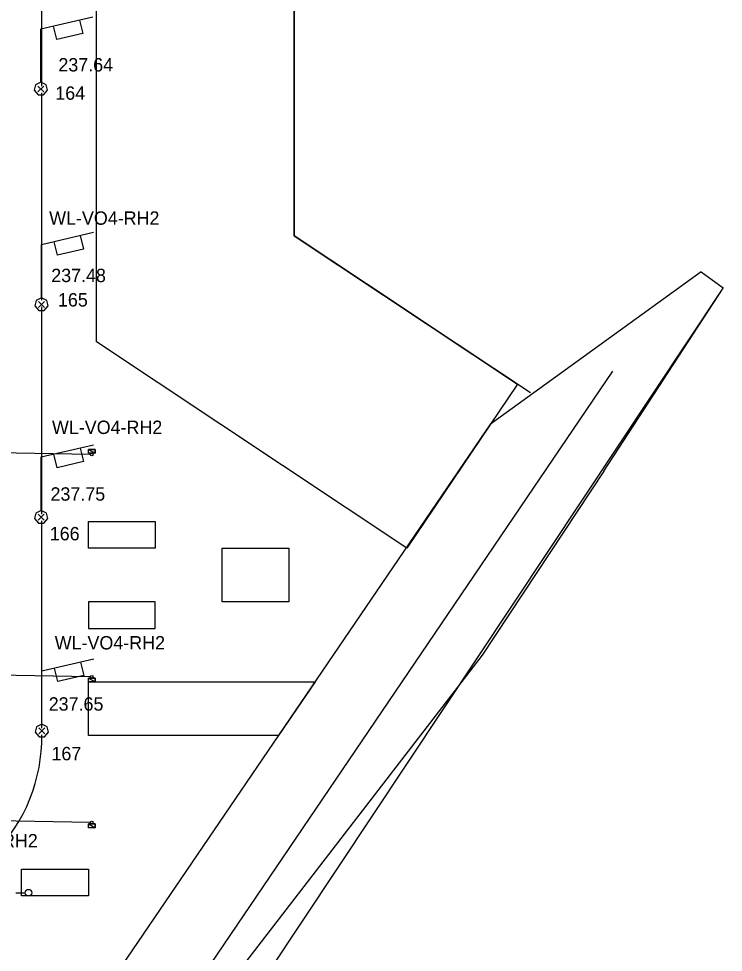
# Model space of a CAD drawing. Extents: x -264222 to -263592, y -1242345 to -1242048.
# Drawn here: x -263787.2 to -263734.5, y -1242254.6 to -1242184.8 of the extents above; entities that cross this region are included whole.
import ezdxf

# ---------------------------------------------------------------- set-up
doc = ezdxf.new("R2010")
doc.units = 0
for name, color, linetype in [('BOD_CISLO', 7, 'Continuous'), ('BOD_SYMBOL', 7, 'Continuous'), ('BOD_VYSKA', 7, 'Continuous'), ('KFA_2D_SITUACIA_DSP', 7, 'Continuous'), ('KFA_SO_62-1_VO_LAMPY_MERANE', 7, 'Continuous'), ('KFA_SO_62-1_VO_POPIS_LAMP_PROJEKT', 7, 'Continuous'), ('KFA_SO_62-1_VO_TRASA_KABLOV_PROJEKT', 7, 'Continuous')]:
    doc.layers.add(name, color=color, linetype=linetype)

msp = doc.modelspace()

# ---------------------------------------------------------------- linework, layer by layer
at = {"layer": 'BOD_SYMBOL'}
for p, q in [((-263785.745, -1242190.259), (-263785.303, -1242189.817)), ((-263785.303, -1242190.259), (-263785.745, -1242189.817)), ((-263785.697, -1242206.378), (-263785.255, -1242205.936)), ((-263785.255, -1242206.378), (-263785.697, -1242205.936)), ((-263785.713, -1242222.277), (-263785.271, -1242221.835)), ((-263785.271, -1242222.277), (-263785.713, -1242221.835)), ((-263785.668, -1242238.262), (-263785.226, -1242237.82)), ((-263785.226, -1242238.262), (-263785.668, -1242237.82))]:
    msp.add_line(p, q, dxfattribs=at)
at = {"layer": 'KFA_2D_SITUACIA_DSP'}
for p, q in [((-263766.58, -1242201.01), (-263766.58, -1242144.85)), ((-263758.42, -1242206.43), (-263766.58, -1242201.01)), ((-263736.134, -1242203.7), (-263751.891, -1242215.1)), ((-263736.134, -1242203.7), (-263734.475, -1242204.91)), ((-263822.88, -1242337.914), (-263734.49, -1242204.937)), ((-263757.19, -1242207.25), (-263758.42, -1242206.43)), ((-263748.89, -1242212.77), (-263757.19, -1242207.25)), ((-263794.898, -1242288.032), (-263742.736, -1242211.145)), ((-263798.899, -1242284.125), (-263751.864, -1242215.081)), ((-263751.891, -1242215.1), (-263751.891, -1242215.1)), ((-263781.968, -1242216.987), (-263781.468, -1242216.987)), ((-263781.968, -1242217.277), (-263781.968, -1242216.987)), ((-263781.968, -1242216.987), (-263781.468, -1242217.277)), ((-263781.968, -1242216.987), (-263781.468, -1242217.277)), ((-263781.468, -1242216.987), (-263781.968, -1242216.987)), ((-263781.468, -1242216.987), (-263781.468, -1242217.277)), ((-263781.468, -1242217.277), (-263781.468, -1242216.987)), ((-263781.818, -1242217.375), (-263790.409, -1242217.218)), ((-263781.468, -1242217.277), (-263781.968, -1242217.277)), ((-263743.421, -1242218.608), (-263752.521, -1242232.37)), ((-263781.968, -1242228.382), (-263781.968, -1242230.382)), ((-263776.968, -1242228.382), (-263781.968, -1242228.382)), ((-263776.968, -1242230.382), (-263776.968, -1242228.382)), ((-263781.968, -1242230.382), (-263776.968, -1242230.382)), ((-263752.521, -1242232.37), (-263782.166, -1242270.821)), ((-263781.818, -1242233.99), (-263790.714, -1242233.827)), ((-263781.968, -1242234.092), (-263781.468, -1242234.092)), ((-263781.968, -1242234.382), (-263781.968, -1242234.092)), ((-263781.968, -1242234.092), (-263781.468, -1242234.382)), ((-263781.968, -1242234.092), (-263781.468, -1242234.382)), ((-263781.468, -1242234.092), (-263781.968, -1242234.092)), ((-263781.468, -1242234.382), (-263781.968, -1242234.382)), ((-263781.968, -1242234.382), (-263771.968, -1242234.382)), ((-263781.968, -1242238.382), (-263781.968, -1242234.382)), ((-263781.968, -1242234.382), (-263781.968, -1242234.382)), ((-263781.468, -1242234.092), (-263781.468, -1242234.382)), ((-263781.468, -1242234.382), (-263781.468, -1242234.092)), ((-263771.968, -1242234.382), (-263765.013, -1242234.382)), ((-263765.013, -1242234.382), (-263767.738, -1242238.382)), ((-263771.968, -1242238.382), (-263781.968, -1242238.382)), ((-263767.738, -1242238.382), (-263771.968, -1242238.382)), ((-263781.818, -1242244.885), (-263790.914, -1242244.718)), ((-263781.968, -1242244.987), (-263781.468, -1242244.987)), ((-263781.968, -1242245.277), (-263781.968, -1242244.987)), ((-263781.968, -1242244.987), (-263781.468, -1242245.277)), ((-263781.968, -1242244.987), (-263781.468, -1242245.277)), ((-263781.468, -1242244.987), (-263781.968, -1242244.987)), ((-263781.468, -1242244.987), (-263781.468, -1242245.277)), ((-263781.468, -1242245.277), (-263781.468, -1242244.987)), ((-263781.468, -1242245.277), (-263781.968, -1242245.277)), ((-263787.393, -1242250.14), (-263786.693, -1242250.14))]:
    msp.add_line(p, q, dxfattribs=at)
for points in [[(-263766.58, -1242083.485), (-263766.58, -1242201.01), (-263749.879, -1242212.113), (-263758.153, -1242224.365), (-263781.364, -1242208.936), (-263781.371, -1242084.903)], [(-263781.968, -1242222.382), (-263776.968, -1242222.382), (-263776.968, -1242224.382), (-263781.968, -1242224.382)], [(-263771.968, -1242224.382), (-263766.968, -1242224.382), (-263766.968, -1242228.382), (-263771.968, -1242228.382)], [(-263786.968, -1242248.382), (-263781.968, -1242248.382), (-263781.968, -1242250.382), (-263786.968, -1242250.382)]]:
    msp.add_lwpolyline(points, close=True, dxfattribs=at)
msp.add_lwpolyline([(-263743.421, -1242218.608), (-263734.49, -1242204.937), (-263734.475, -1242204.91), (-263734.475, -1242204.91)], dxfattribs=at)
for centre, radius in [((-263781.718, -1242217.377), 0.1), ((-263781.718, -1242233.992), 0.1), ((-263781.718, -1242244.887), 0.1), ((-263786.443, -1242250.14), 0.25)]:
    msp.add_circle(centre, radius, dxfattribs=at)
at = {"layer": 'KFA_SO_62-1_VO_LAMPY_MERANE'}
for p, q in [((-263785.574, -1242190.038), (-263785.474, -1242190.038)), ((-263785.524, -1242190.038), (-263785.524, -1242190.038)), ((-263785.526, -1242206.157), (-263785.426, -1242206.157)), ((-263785.476, -1242206.157), (-263785.476, -1242206.157)), ((-263785.542, -1242222.056), (-263785.442, -1242222.056)), ((-263785.492, -1242222.056), (-263785.492, -1242222.056)), ((-263785.497, -1242238.041), (-263785.397, -1242238.041)), ((-263785.447, -1242238.041), (-263785.447, -1242238.041))]:
    msp.add_line(p, q, dxfattribs=at)
for points in [[(-263785.524, -1242189.538), (-263785.924, -1242189.738), (-263786.024, -1242190.138), (-263785.724, -1242190.488), (-263785.324, -1242190.488), (-263785.024, -1242190.138), (-263785.124, -1242189.738), (-263785.524, -1242189.538), (-263785.524, -1242185.538), (-263781.624, -1242184.638)], [(-263782.624, -1242184.888), (-263782.374, -1242185.888), (-263784.324, -1242186.338), (-263784.574, -1242185.338)], [(-263785.476, -1242205.657), (-263785.876, -1242205.857), (-263785.976, -1242206.257), (-263785.676, -1242206.607), (-263785.276, -1242206.607), (-263784.976, -1242206.257), (-263785.076, -1242205.857), (-263785.476, -1242205.657), (-263785.476, -1242201.657), (-263781.576, -1242200.757)], [(-263782.576, -1242201.007), (-263782.326, -1242202.007), (-263784.276, -1242202.457), (-263784.526, -1242201.457)], [(-263785.492, -1242221.556), (-263785.892, -1242221.756), (-263785.992, -1242222.156), (-263785.692, -1242222.506), (-263785.292, -1242222.506), (-263784.992, -1242222.156), (-263785.092, -1242221.756), (-263785.492, -1242221.556), (-263785.492, -1242217.556), (-263781.592, -1242216.656)], [(-263782.592, -1242216.906), (-263782.342, -1242217.906), (-263784.292, -1242218.356), (-263784.542, -1242217.356)], [(-263785.447, -1242237.541), (-263785.847, -1242237.741), (-263785.947, -1242238.141), (-263785.647, -1242238.491), (-263785.247, -1242238.491), (-263784.947, -1242238.141), (-263785.047, -1242237.741), (-263785.447, -1242237.541), (-263785.447, -1242233.541), (-263781.547, -1242232.641)], [(-263782.547, -1242232.891), (-263782.297, -1242233.891), (-263784.247, -1242234.341), (-263784.497, -1242233.341)]]:
    msp.add_lwpolyline(points, dxfattribs=at)
at = {"layer": 'KFA_SO_62-1_VO_TRASA_KABLOV_PROJEKT'}
for p, q in [((-263785.465, -1242174.333), (-263785.465, -1242189.833)), ((-263785.465, -1242190.333), (-263785.465, -1242205.833)), ((-263785.465, -1242206.333), (-263785.465, -1242221.833)), ((-263785.465, -1242222.333), (-263785.465, -1242237.833))]:
    msp.add_line(p, q, dxfattribs=at)
msp.add_arc((-263797.796, -1242238.53), 12.345, 269.80426, 0.91793, dxfattribs=at)

# ---------------------------------------------------------------- texts
at = {"layer": 'BOD_CISLO'}
for s, p in [('164', (-263784.442, -1242190.846)), ('165', (-263784.243, -1242206.305)), ('166', (-263784.854, -1242223.79)), ('167', (-263784.728, -1242240.237))]:
    msp.add_text(s, height=1, dxfattribs=at).set_placement(p)
at = {"layer": 'BOD_VYSKA'}
for s, p in [('237.64', (-263784.21, -1242188.731)), ('237.48', (-263784.744, -1242204.481)), ('237.75', (-263784.799, -1242220.824)), ('237.65', (-263784.932, -1242236.525))]:
    msp.add_text(s, height=1, dxfattribs=at).set_placement(p)
at = {"layer": 'KFA_SO_62-1_VO_POPIS_LAMP_PROJEKT'}
for p in [(-263784.898, -1242200.193), (-263784.688, -1242215.838), (-263784.483, -1242231.95), (-263793.999, -1242246.75)]:
    msp.add_text('WL-VO4-RH2', height=1, dxfattribs=at).set_placement(p)

doc.saveas('drawing.dxf')
